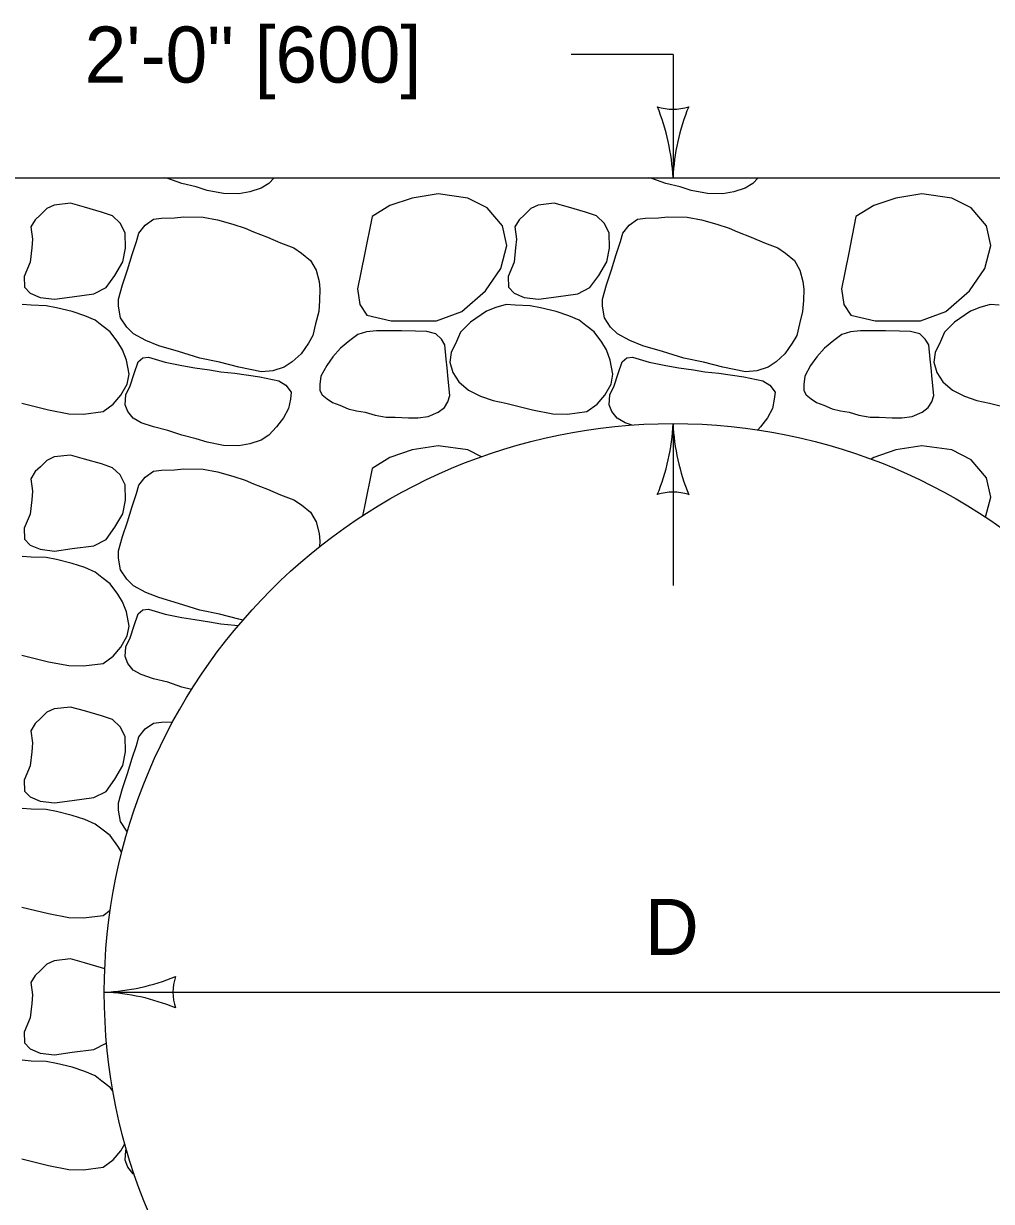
# Model space of a CAD drawing. Extents: x 49991.4 to 50021, y 49987.6 to 50011.4.
# Drawn here: x 50006.087 to 50007.124, y 50008.582 to 50009.843 of the extents above; entities that cross this region are included whole.
import ezdxf

# ---------------------------------------------------------------- set-up
doc = ezdxf.new("R2010")
doc.units = 0
for name, color, linetype in [('Default', 7, 'Continuous'), ('Level 1', 7, 'Continuous'), ('Level 2', 7, 'Continuous'), ('Level 3', 7, 'Continuous')]:
    doc.layers.add(name, color=color, linetype=linetype)

msp = doc.modelspace()

# ---------------------------------------------------------------- linework, layer by layer
at = {"layer": 'Default'}
for points in [[(50006.3556, 50009.6783), (50006.35, 50009.6722), (50006.3418, 50009.667), (50006.3295, 50009.6633), (50006.318, 50009.661), (50006.3016, 50009.6614), (50006.284, 50009.6648), (50006.2721, 50009.6685), (50006.2569, 50009.6722), (50006.2417, 50009.6775), (50006.2383, 50009.6783)], [(50006.8739, 50009.6783), (50006.8683, 50009.6722), (50006.8601, 50009.667), (50006.8478, 50009.6633), (50006.8363, 50009.661), (50006.8199, 50009.6614), (50006.8022, 50009.6648), (50006.7903, 50009.6685), (50006.7751, 50009.6722), (50006.76, 50009.6775), (50006.7565, 50009.6783)], [(50006.0854, 50009.4368), (50006.1141, 50009.4297), (50006.1358, 50009.4256), (50006.1514, 50009.4253), (50006.1724, 50009.4279), (50006.1834, 50009.4357), (50006.1916, 50009.4454), (50006.1982, 50009.4574), (50006.2003, 50009.4678), (50006.1974, 50009.4831), (50006.1933, 50009.4939), (50006.1884, 50009.5021), (50006.1802, 50009.5133), (50006.1711, 50009.5201), (50006.1641, 50009.5257), (50006.1531, 50009.5305), (50006.1395, 50009.535), (50006.1227, 50009.5391), (50006.1116, 50009.5413), (50006.0956, 50009.5417), (50006.0858, 50009.5424)], [(50007.1321, 50009.5417), (50007.1223, 50009.5424), (50007.1112, 50009.5395), (50007.1014, 50009.5354), (50007.0841, 50009.5238), (50007.0734, 50009.513), (50007.0693, 50009.5029), (50007.0636, 50009.4913), (50007.062, 50009.4809), (50007.0652, 50009.4697), (50007.0718, 50009.4596), (50007.0821, 50009.451), (50007.0948, 50009.4443), (50007.1083, 50009.4398), (50007.1219, 50009.4368), (50007.1506, 50009.4297)], [(50006.7389, 50009.4135), (50006.7316, 50009.4159), (50006.723, 50009.4208), (50006.7173, 50009.4279), (50006.7144, 50009.4353), (50006.7152, 50009.4458), (50006.7197, 50009.4555), (50006.7239, 50009.4686), (50006.7284, 50009.4812), (50006.7333, 50009.4853), (50006.7394, 50009.4861), (50006.7571, 50009.4809), (50006.7751, 50009.4771), (50006.7891, 50009.4749), (50006.8047, 50009.4727), (50006.817, 50009.4704), (50006.8318, 50009.4689), (50006.8585, 50009.4652), (50006.879, 50009.4607), (50006.8864, 50009.4562), (50006.8921, 50009.4488), (50006.8913, 50009.4413), (50006.8892, 50009.4312), (50006.8839, 50009.4212), (50006.8765, 50009.4115), (50006.8736, 50009.4082)], [(50006.5777, 50009.3794), (50006.5632, 50009.3868), (50006.5312, 50009.3913), (50006.5033, 50009.3868), (50006.4795, 50009.3786), (50006.4605, 50009.367), (50006.4524, 50009.3264), (50006.4503, 50009.3163)], [(50007.1176, 50009.3148), (50007.1233, 50009.3361), (50007.1184, 50009.357), (50007.102, 50009.3764), (50007.0814, 50009.3868), (50007.0494, 50009.3913), (50007.0215, 50009.3868), (50006.9977, 50009.3786), (50006.9949, 50009.3769)], [(50006.3224, 50009.2046), (50006.318, 50009.2055), (50006.2971, 50009.2111), (50006.2761, 50009.2152), (50006.2532, 50009.2223), (50006.2322, 50009.2287), (50006.2183, 50009.2343), (50006.2052, 50009.2414), (50006.1978, 50009.2484), (50006.1912, 50009.2585), (50006.1891, 50009.2708), (50006.1891, 50009.2787), (50006.1933, 50009.294), (50006.1986, 50009.31), (50006.2035, 50009.3264), (50006.2084, 50009.3403), (50006.2109, 50009.3492), (50006.2175, 50009.3578), (50006.2265, 50009.3641), (50006.2351, 50009.3653), (50006.2491, 50009.3656), (50006.2589, 50009.3667), (50006.2798, 50009.3664), (50006.295, 50009.3634), (50006.3114, 50009.3589), (50006.3246, 50009.3544), (50006.3336, 50009.3507), (50006.3484, 50009.3447), (50006.3623, 50009.3388), (50006.3767, 50009.3335), (50006.3849, 50009.3279), (50006.3947, 50009.3201), (50006.4005, 50009.3097), (50006.4038, 50009.2973), (50006.4046, 50009.2891), (50006.4044, 50009.2832)], [(50006.0854, 50009.1671), (50006.1141, 50009.16), (50006.1358, 50009.1559), (50006.1514, 50009.1555), (50006.1724, 50009.1581), (50006.1834, 50009.166), (50006.1916, 50009.1757), (50006.1982, 50009.1876), (50006.2003, 50009.1981), (50006.1974, 50009.2134), (50006.1933, 50009.2242), (50006.1884, 50009.2324), (50006.1802, 50009.2436), (50006.1711, 50009.2503), (50006.1641, 50009.2559), (50006.1531, 50009.2608), (50006.1395, 50009.2653), (50006.1227, 50009.2694), (50006.1116, 50009.2716), (50006.0956, 50009.272), (50006.0858, 50009.2727)], [(50006.2673, 50009.1302), (50006.2569, 50009.1328), (50006.2417, 50009.138), (50006.2265, 50009.1417), (50006.2134, 50009.1462), (50006.2048, 50009.1511), (50006.199, 50009.1581), (50006.1962, 50009.1656), (50006.197, 50009.1761), (50006.2015, 50009.1858), (50006.2056, 50009.1988), (50006.2101, 50009.2115), (50006.215, 50009.2156), (50006.2212, 50009.2164), (50006.2388, 50009.2111), (50006.2569, 50009.2074), (50006.2708, 50009.2052), (50006.2864, 50009.2029), (50006.2987, 50009.2007), (50006.3135, 50009.1992), (50006.3173, 50009.1987)], [(50006.1986, 50008.9779), (50006.1978, 50008.9787), (50006.1912, 50008.9888), (50006.1891, 50009.0011), (50006.1891, 50009.0089), (50006.1933, 50009.0242), (50006.1986, 50009.0403), (50006.2035, 50009.0567), (50006.2084, 50009.0705), (50006.2109, 50009.0795), (50006.2175, 50009.0881), (50006.2265, 50009.0944), (50006.2351, 50009.0955), (50006.2472, 50009.0958)], [(50006.1925, 50008.9557), (50006.1884, 50008.9627), (50006.1802, 50008.9739), (50006.1711, 50008.9806), (50006.1641, 50008.9862), (50006.1531, 50008.991), (50006.1395, 50008.9955), (50006.1227, 50008.9996), (50006.1116, 50009.0019), (50006.0956, 50009.0022), (50006.0858, 50009.003)], [(50006.0854, 50008.8974), (50006.1141, 50008.8903), (50006.1358, 50008.8862), (50006.1514, 50008.8858), (50006.1724, 50008.8884), (50006.1802, 50008.894)], [(50006.1744, 50008.8312), (50006.1707, 50008.8324), (50006.1527, 50008.8377), (50006.1375, 50008.8418), (50006.1202, 50008.8399), (50006.1124, 50008.8362), (50006.1055, 50008.8295), (50006.0997, 50008.8242), (50006.0952, 50008.8164), (50006.0968, 50008.8033), (50006.096, 50008.794), (50006.0944, 50008.7787), (50006.0878, 50008.7634), (50006.0882, 50008.7518), (50006.0944, 50008.7455), (50006.1051, 50008.741), (50006.1206, 50008.7391), (50006.1395, 50008.7418), (50006.1625, 50008.7447), (50006.1756, 50008.7515), (50006.1762, 50008.7523)], [(50006.1832, 50008.7), (50006.1802, 50008.7041), (50006.1711, 50008.7109), (50006.1641, 50008.7165), (50006.1531, 50008.7213), (50006.1395, 50008.7258), (50006.1227, 50008.7299), (50006.1116, 50008.7321), (50006.0956, 50008.7325), (50006.0858, 50008.7333)], [(50006.0854, 50008.6276), (50006.1141, 50008.6206), (50006.1358, 50008.6164), (50006.1514, 50008.6161), (50006.1724, 50008.6187), (50006.1834, 50008.6265), (50006.1916, 50008.6362), (50006.1959, 50008.6439)], [(50006.206, 50008.6109), (50006.2048, 50008.6116), (50006.199, 50008.6187), (50006.1962, 50008.6262), (50006.197, 50008.6366), (50006.1976, 50008.6378)]]:
    msp.add_lwpolyline(points, dxfattribs=at)
for points in [[(50006.4605, 50009.6368), (50006.4524, 50009.5961), (50006.445, 50009.5595), (50006.4475, 50009.5424), (50006.4549, 50009.5312), (50006.4811, 50009.5252), (50006.5295, 50009.5252), (50006.5566, 50009.5349), (50006.5821, 50009.5573), (50006.5985, 50009.5812), (50006.605, 50009.6058), (50006.6001, 50009.6267), (50006.5837, 50009.6461), (50006.5632, 50009.6566), (50006.5312, 50009.661), (50006.5033, 50009.6566), (50006.4795, 50009.6484)], [(50006.9787, 50009.6368), (50006.9706, 50009.5961), (50006.9633, 50009.5595), (50006.9657, 50009.5424), (50006.9731, 50009.5312), (50006.9994, 50009.5252), (50007.0478, 50009.5252), (50007.0749, 50009.5349), (50007.1003, 50009.5573), (50007.1167, 50009.5812), (50007.1233, 50009.6058), (50007.1184, 50009.6267), (50007.102, 50009.6461), (50007.0814, 50009.6566), (50007.0494, 50009.661), (50007.0215, 50009.6566), (50006.9977, 50009.6484)], [(50006.1202, 50009.6491), (50006.1124, 50009.6454), (50006.1055, 50009.6386), (50006.0997, 50009.6334), (50006.0952, 50009.6256), (50006.0968, 50009.6125), (50006.096, 50009.6032), (50006.0944, 50009.5879), (50006.0878, 50009.5726), (50006.0882, 50009.561), (50006.0944, 50009.5547), (50006.1051, 50009.5502), (50006.1206, 50009.5483), (50006.1395, 50009.5509), (50006.1625, 50009.5539), (50006.1756, 50009.5607), (50006.1851, 50009.5737), (50006.1937, 50009.5883), (50006.1966, 50009.6028), (50006.1962, 50009.6192), (50006.1908, 50009.6297), (50006.1826, 50009.6375), (50006.1707, 50009.6416), (50006.1527, 50009.6469), (50006.1375, 50009.651)], [(50006.6385, 50009.6491), (50006.6307, 50009.6454), (50006.6237, 50009.6386), (50006.618, 50009.6334), (50006.6135, 50009.6256), (50006.6151, 50009.6125), (50006.6143, 50009.6032), (50006.6126, 50009.5879), (50006.6061, 50009.5726), (50006.6065, 50009.561), (50006.6126, 50009.5547), (50006.6233, 50009.5502), (50006.6389, 50009.5483), (50006.6578, 50009.5509), (50006.6808, 50009.5539), (50006.6939, 50009.5607), (50006.7033, 50009.5737), (50006.7119, 50009.5883), (50006.7148, 50009.6028), (50006.7144, 50009.6192), (50006.7091, 50009.6297), (50006.7009, 50009.6375), (50006.689, 50009.6416), (50006.6709, 50009.6469), (50006.6557, 50009.651)], [(50006.2351, 50009.635), (50006.2491, 50009.6354), (50006.2589, 50009.6365), (50006.2798, 50009.6361), (50006.295, 50009.6331), (50006.3114, 50009.6286), (50006.3246, 50009.6242), (50006.3336, 50009.6204), (50006.3484, 50009.6145), (50006.3623, 50009.6085), (50006.3767, 50009.6033), (50006.3849, 50009.5977), (50006.3947, 50009.5898), (50006.4005, 50009.5794), (50006.4038, 50009.5671), (50006.4046, 50009.5589), (50006.4042, 50009.5469), (50006.4034, 50009.535), (50006.4001, 50009.5219), (50006.3972, 50009.5092), (50006.3923, 50009.501), (50006.3845, 50009.4898), (50006.375, 50009.4812), (50006.3664, 50009.4753), (50006.3541, 50009.4715), (50006.3422, 50009.4704), (50006.318, 50009.4753), (50006.2971, 50009.4809), (50006.2761, 50009.485), (50006.2532, 50009.4921), (50006.2322, 50009.4984), (50006.2183, 50009.504), (50006.2052, 50009.5111), (50006.1978, 50009.5182), (50006.1912, 50009.5283), (50006.1891, 50009.5406), (50006.1891, 50009.5484), (50006.1933, 50009.5637), (50006.1986, 50009.5798), (50006.2035, 50009.5962), (50006.2084, 50009.61), (50006.2109, 50009.6189), (50006.2175, 50009.6275), (50006.2265, 50009.6339)], [(50006.7534, 50009.635), (50006.7673, 50009.6354), (50006.7772, 50009.6365), (50006.7981, 50009.6361), (50006.8133, 50009.6331), (50006.8297, 50009.6286), (50006.8428, 50009.6242), (50006.8519, 50009.6204), (50006.8666, 50009.6145), (50006.8806, 50009.6085), (50006.8949, 50009.6033), (50006.9031, 50009.5977), (50006.913, 50009.5898), (50006.9187, 50009.5794), (50006.922, 50009.5671), (50006.9228, 50009.5589), (50006.9224, 50009.5469), (50006.9216, 50009.535), (50006.9183, 50009.5219), (50006.9155, 50009.5092), (50006.9105, 50009.501), (50006.9027, 50009.4898), (50006.8933, 50009.4812), (50006.8847, 50009.4753), (50006.8724, 50009.4715), (50006.8605, 50009.4704), (50006.8363, 50009.4753), (50006.8153, 50009.4809), (50006.7944, 50009.485), (50006.7714, 50009.4921), (50006.7505, 50009.4984), (50006.7365, 50009.504), (50006.7234, 50009.5111), (50006.716, 50009.5182), (50006.7095, 50009.5283), (50006.7074, 50009.5406), (50006.7074, 50009.5484), (50006.7115, 50009.5637), (50006.7168, 50009.5798), (50006.7218, 50009.5962), (50006.7267, 50009.61), (50006.7292, 50009.6189), (50006.7357, 50009.6275), (50006.7447, 50009.6339)], [(50006.5831, 50009.5354), (50006.5659, 50009.5238), (50006.5552, 50009.513), (50006.5511, 50009.5029), (50006.5453, 50009.4913), (50006.5437, 50009.4809), (50006.547, 50009.4697), (50006.5536, 50009.4596), (50006.5638, 50009.451), (50006.5765, 50009.4443), (50006.5901, 50009.4398), (50006.6036, 50009.4368), (50006.6323, 50009.4297), (50006.6541, 50009.4256), (50006.6697, 50009.4253), (50006.6906, 50009.4279), (50006.7017, 50009.4357), (50006.7099, 50009.4454), (50006.7165, 50009.4574), (50006.7185, 50009.4678), (50006.7156, 50009.4831), (50006.7115, 50009.4939), (50006.7066, 50009.5021), (50006.6984, 50009.5133), (50006.6894, 50009.5201), (50006.6824, 50009.5257), (50006.6713, 50009.5305), (50006.6578, 50009.535), (50006.641, 50009.5391), (50006.6299, 50009.5413), (50006.6139, 50009.5417), (50006.604, 50009.5424), (50006.5929, 50009.5395)], [(50006.4547, 50009.5133), (50006.4452, 50009.5104), (50006.4366, 50009.504), (50006.4267, 50009.4958), (50006.4185, 50009.4865), (50006.412, 50009.4771), (50006.4058, 50009.4659), (50006.4046, 50009.457), (50006.4046, 50009.4506), (50006.4071, 50009.4458), (50006.4124, 50009.4417), (50006.4181, 50009.4376), (50006.4259, 50009.4346), (50006.435, 50009.4309), (50006.444, 50009.4286), (50006.453, 50009.4271), (50006.4637, 50009.4241), (50006.4756, 50009.4219), (50006.4854, 50009.4219), (50006.4994, 50009.4212), (50006.5096, 50009.4212), (50006.5207, 50009.4227), (50006.5314, 50009.4271), (50006.538, 50009.4324), (50006.5417, 50009.4383), (50006.5437, 50009.445), (50006.5421, 50009.4626), (50006.5408, 50009.4749), (50006.54, 50009.4839), (50006.5384, 50009.4992), (50006.5347, 50009.5055), (50006.5289, 50009.5111), (50006.5191, 50009.5137), (50006.5072, 50009.5141), (50006.492, 50009.5145), (50006.4768, 50009.5145), (50006.4653, 50009.5145)], [(50006.9729, 50009.5133), (50006.9635, 50009.5104), (50006.9549, 50009.504), (50006.945, 50009.4958), (50006.9368, 50009.4865), (50006.9302, 50009.4771), (50006.9241, 50009.4659), (50006.9228, 50009.457), (50006.9228, 50009.4506), (50006.9253, 50009.4458), (50006.9306, 50009.4417), (50006.9364, 50009.4376), (50006.9442, 50009.4346), (50006.9532, 50009.4309), (50006.9622, 50009.4286), (50006.9713, 50009.4271), (50006.9819, 50009.4241), (50006.9938, 50009.4219), (50007.0037, 50009.4219), (50007.0176, 50009.4212), (50007.0279, 50009.4212), (50007.039, 50009.4227), (50007.0496, 50009.4271), (50007.0562, 50009.4324), (50007.0599, 50009.4383), (50007.062, 50009.445), (50007.0603, 50009.4626), (50007.0591, 50009.4749), (50007.0583, 50009.4839), (50007.0566, 50009.4992), (50007.0529, 50009.5055), (50007.0472, 50009.5111), (50007.0373, 50009.5137), (50007.0254, 50009.5141), (50007.0103, 50009.5145), (50006.9951, 50009.5145), (50006.9836, 50009.5145)], [(50006.2101, 50009.4812), (50006.215, 50009.4853), (50006.2212, 50009.4861), (50006.2388, 50009.4809), (50006.2569, 50009.4771), (50006.2708, 50009.4749), (50006.2864, 50009.4727), (50006.2987, 50009.4704), (50006.3135, 50009.4689), (50006.3402, 50009.4652), (50006.3607, 50009.4607), (50006.3681, 50009.4562), (50006.3738, 50009.4488), (50006.373, 50009.4413), (50006.371, 50009.4312), (50006.3656, 50009.4212), (50006.3583, 50009.4115), (50006.35, 50009.4025), (50006.3418, 50009.3973), (50006.3295, 50009.3935), (50006.318, 50009.3913), (50006.3016, 50009.3917), (50006.284, 50009.395), (50006.2721, 50009.3988), (50006.2569, 50009.4025), (50006.2417, 50009.4077), (50006.2265, 50009.4115), (50006.2134, 50009.4159), (50006.2048, 50009.4208), (50006.199, 50009.4279), (50006.1962, 50009.4353), (50006.197, 50009.4458), (50006.2015, 50009.4555), (50006.2056, 50009.4686)], [(50006.1202, 50009.3794), (50006.1124, 50009.3756), (50006.1055, 50009.3689), (50006.0997, 50009.3637), (50006.0952, 50009.3559), (50006.0968, 50009.3428), (50006.096, 50009.3335), (50006.0944, 50009.3182), (50006.0878, 50009.3029), (50006.0882, 50009.2913), (50006.0944, 50009.2849), (50006.1051, 50009.2805), (50006.1206, 50009.2786), (50006.1395, 50009.2812), (50006.1625, 50009.2842), (50006.1756, 50009.2909), (50006.1851, 50009.304), (50006.1937, 50009.3185), (50006.1966, 50009.3331), (50006.1962, 50009.3495), (50006.1908, 50009.36), (50006.1826, 50009.3678), (50006.1707, 50009.3719), (50006.1527, 50009.3771), (50006.1375, 50009.3812)], [(50006.1202, 50009.1096), (50006.1124, 50009.1059), (50006.1055, 50009.0992), (50006.0997, 50009.094), (50006.0952, 50009.0861), (50006.0968, 50009.0731), (50006.096, 50009.0637), (50006.0944, 50009.0484), (50006.0878, 50009.0331), (50006.0882, 50009.0216), (50006.0944, 50009.0152), (50006.1051, 50009.0107), (50006.1206, 50009.0089), (50006.1395, 50009.0115), (50006.1625, 50009.0145), (50006.1756, 50009.0212), (50006.1851, 50009.0343), (50006.1937, 50009.0488), (50006.1966, 50009.0634), (50006.1962, 50009.0798), (50006.1908, 50009.0902), (50006.1826, 50009.0981), (50006.1707, 50009.1022), (50006.1527, 50009.1074), (50006.1375, 50009.1115)]]:
    msp.add_lwpolyline(points, close=True, dxfattribs=at)
at = {"layer": 'Level 1'}
msp.add_line((50005.6473, 50009.6783), (50007.9186, 50009.6783), dxfattribs=at)
msp.add_circle((50006.7828, 50008.8061), 0.609, dxfattribs=at)
at = {"layer": 'Level 3'}
for p, q in [((50006.7828, 50009.8102), (50006.6739, 50009.8102)), ((50006.7828, 50009.8102), (50006.7828, 50009.6783)), ((50006.7828, 50009.415), (50006.7828, 50009.2416)), ((50006.1739, 50008.8061), (50007.3918, 50008.8061))]:
    msp.add_line(p, q, dxfattribs=at)
for centre, radius, start, end in [((50006.7828, 50009.8065), 0.0548, 252.1388, 287.8612), ((50006.5501, 50009.6668), 0.233, 2.8273, 22.0772), ((50007.0049, 50009.6691), 0.2223, 157.456, 177.6395), ((50006.5607, 50009.4242), 0.2223, 337.456, 357.6395), ((50007.0155, 50009.4265), 0.233, 182.8273, 202.0772), ((50006.7828, 50009.2868), 0.0548, 72.1388, 107.8612), ((50006.1624, 50009.0388), 0.233, 272.8273, 292.0772), ((50006.3021, 50008.8061), 0.0548, 162.1388, 197.8612), ((50006.1647, 50008.584), 0.2223, 67.456, 87.6395)]:
    msp.add_arc(centre, radius, start, end, dxfattribs=at)

# ---------------------------------------------------------------- texts
at = {"layer": 'Level 2'}
for s, p in [('2\'-0" [600]', (50006.1527, 50009.7802)), ('D', (50006.7525, 50008.8461))]:
    msp.add_text(s, height=0.06, dxfattribs=at).set_placement(p)

doc.saveas('drawing.dxf')
